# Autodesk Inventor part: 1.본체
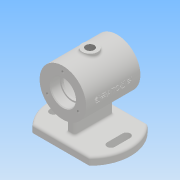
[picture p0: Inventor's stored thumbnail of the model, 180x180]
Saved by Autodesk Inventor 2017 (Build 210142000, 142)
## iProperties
Part Number: 1.본체
Material: 일반
Document SubType Name: Modeling
Designer: user
Density: 1 g/cm^3
Appearance: 기본값
Author: user
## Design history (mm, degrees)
sketch "스케치1"
  geometry: L1 (-37.5, -36.742)-(-37.5, 36.742); L2 (37.5, 36.742)-(37.5, -36.742); L3 (-37.5, -36.742)-(37.5, -36.742); L4 (-37.5, 36.742)-(37.5, 36.742); L5 (37.5, 36.742)-(0, 36.742); L6 (-10, 36.742)-(10, 36.742); L7 (-10, 36.742)-(10, 36.742); L8 (-52.5, 0)-(52.5, 0); L9 (0, 0)-(0, -37); L10 (10, -37)-(-10, -37); L11 (10, -37)-(-10, -37); L12 (10, -32)-(-10, -32); L13 (-10, -42)-(10, -42); L14 (-10, 42)-(10, 42); L15 (10, 32)-(-10, 32); A1 r 52.5 centre (0, 0) between (37.5, 36.742) and (-37.5, 36.742); A2 r 52.5 centre (0, 0) between (37.5, -36.742) and (37.5, 36.742); A3 r 52.5 centre (0, 0) between (-37.5, -36.742) and (37.5, -36.742); A4 r 52.5 centre (0, 0) between (-37.5, 36.742) and (-37.5, -36.742); A5 r 5 centre (10, -37) between (10, -42) and (10, -32); A6 r 5 centre (-10, -37) between (-10, -32) and (-10, -42); A7 r 5 centre (10, 37) between (10, 32) and (10, 42); A8 r 5 centre (-10, 37) between (-10, 42) and (-10, 32); 3 further points
  constraints: 34 end point, 18 point on circle, 8 centre point, 6 symmetric about line, 5 coincident, 5 midpoint, 4 tangent, 3 horizontal, 3 parallel, 1 collinear, 1 vertical, 2 other
  dimensions: "d0" = 105 diameter of A1; "d2" = 73.48469 distance of L2.start L2.end; "d3" = 75 distance between parallel lines of L2 L1; "d13" = 37.5 distance of L2.start L5.end; "d75" = 37 distance of L9.end L9.start; "d76" = 20 distance of L10.start L10.end; "d77" = 20 distance of L6.start L6.end; "d78" = 10 diameter of A6
extrude "돌출1" new body sketch "스케치1" distance "d4" = 10; taper "d5" = 0 deg
sketch "스케치2"
  geometry: L1 (0, 0)-(0, 62); L2 (-25, 0)-(25, 0); L3 (-25, 0)-(-25, 62); L4 (-25, 62)-(25, 62); L5 (25, 62)-(25, 0)
  constraints: 10 end point, 2 midpoint, 2 vertical, 1 horizontal, 1 parallel, 1 perpendicular
  dimensions: "d6" = 62 distance of L1.end L1.start; "d7" = 50 distance of L2.start L2.end
extrude "돌출2" join sketch "스케치2" stored distance "d8" = 10; taper "d9" = 0 deg
sketch "스케치3"
  geometry: L1 (-5, 62)-(5, 62) reference; C1 r 30 at (0, 62); 2 further points
  constraints: 1 centre point, 1 coincident, 1 midpoint
  dimensions: "d10" = 60 diameter of C1
extrude "돌출3" join sketch "스케치3" stored distance "d11" = 70; taper "d12" = 0 deg
sketch "스케치4"
  geometry: L1 (35, 32)-(35, 92) reference; L2 (35, 62)-(-35, 62); L3 (-35, 92)-(-35, 32) reference; L4 (35, 62)-(35, 78); L5 (35, 78)-(23, 78); L6 (23, 78)-(23, 76); L7 (23, 76)-(20, 76); L8 (20, 76)-(20, 87); L9 (20, 87)-(-20, 87); L10 (-20, 87)-(-20, 76); L11 (-20, 76)-(-23, 76); L12 (-23, 76)-(-23, 78); L13 (-23, 78)-(-35, 78); L14 (-35, 78)-(-35, 62); 1 further point
  constraints: 24 end point, 7 perpendicular, 6 point on line, 2 midpoint, 1 collinear, 1 vertical
  dimensions: "d20" = 12 distance of L4.end L5.end; "d21" = 28 diameter of L7 L2; "d22" = 32 diameter of L5 L2; "d23" = 50 diameter of L9 L2; "d24" = 3 distance of L6.end L7.end; "d25" = 40 distance of L8.end L9.end
node "작업 평면1"
sketch "스케치5"
  geometry: C1 r 10 at (0, 0); 1 further point
  constraints: 1 centre point, 1 coincident
  dimensions: "d28" = 20 diameter of C1
extrude "돌출5" join sketch "스케치5" distance "d29" = 20; taper "d30" = 0 deg
revolve "회전2" stored, may be unused: angle "d31" = 90 deg
sketch "스케치6"
  geometry: C1 r 10 at (0, 0) reference; 1 further point
  constraints: 1 coincident
hole "구멍1" sketch "스케치6" at (0, 0) diameter "d32" = 10.917; stored, may be unused: countersink angle "d36" = 90 deg, drill point angle "d38" = 118 deg; dims "d33" = 24, "d34" = 4, "d35" = 2, "d37" = 29.1
sketch "스케치7" dims "d48" = 46
  geometry: L1 (-23, 0)-(0, 0); L2 (11.5, -19.919)-(0, 0); L3 (11.5, 19.919)-(0, 0); L4 (0, 0)-(62, 0); C1 r 16 at (0, 0) reference; C2 r 30 at (0, 0) reference; 6 further points
  constraints: 8 end point, 6 coincident, 2 horizontal, 1 horizontal alignment, 1 point on line, 22 other
  dimensions: "d46" = 360 deg dimension on point (0, 0) L1.start (derived); "d74" = 23 distance of L3.start L3.end
hole "구멍2" sketch "스케치7" at (-23, 0), (11.5, -19.919), (11.5, 19.919) diameter "d49" = 3.242; stored, may be unused: countersink angle "d53" = 90 deg, drill point angle "d55" = 118 deg; dims "d50" = 8, "d51" = 4, "d52" = 2, "d54" = 10
fillet "모깎기1" dims "d56" = 3
fillet "모깎기2" dims "d57" = 3
chamfer "모따기1" distance "d58" = 1; stored, may be unused: second distance "d59" = 2, angle "d60" = 45 deg
chamfer "모따기2" distance "d61" = 1; stored, may be unused: second distance "d62" = 2, angle "d63" = 45 deg
fillet "모깎기3" dims "d64" = 3
fillet "모깎기4" dims "d65" = 3
fillet "모깎기5" dims "d66" = 3
fillet "모깎기6" dims "d67" = 3
fillet "모깎기7" dims "d68" = 0.3
node "작업 평면2"
sketch "스케치8"
  geometry: L1 (0, 0)-(0, 95); L2 (-10, 95)-(10, 95) reference; L3 (35, 32)-(35, 92) reference; L4 (-35, 92)-(-35, 32) reference; L5 (-35, 62)-(35, 62); 2 further points
  constraints: 4 end point, 4 midpoint, 1 coincident, 1 other
  dimensions: "d85" = 35 distance between parallel lines of L4 L1 (derived); "d86" = 30 distance from line of L4.start L5 (derived)
feature "엠보싱1" sketch "스케치8" dims "d0" = 105, "d2" = 73.48469, "d3" = 75, "d13" = 37.5, "d72" = 0.5, "d73" = 0, "d75" = 37, "d76" = 20, "d77" = 20, "d78" = 10
sketch "스케치9"
  geometry: L1 (37.5, -35.496)-(37.5, 35.496) reference; L2 (-37.5, -35.496)-(-37.5, 35.496) reference; L3 (-37.5, 0)-(37.5, 0); L4 (0, 0)-(0, 37); L5 (-10, 37)-(10, 37); L6 (-10, 37)-(10, 37); L7 (-10, 32)-(10, 32); L8 (10, 42)-(-10, 42); L9 (-10, -32)-(10, -32); L10 (10, -42)-(-10, -42); A1 r 52.5 centre (0, 0) between (36.591, 37.648) and (-36.591, 37.648) reference; A2 r 5 centre (-10, 37) between (-10, 42) and (-10, 32); A3 r 5 centre (10, 37) between (10, 32) and (10, 42); A4 r 5 centre (10, -37) between (10, -42) and (10, -32); A5 r 5 centre (-10, -37) between (-10, -32) and (-10, -42); 1 further point
  constraints: 18 end point, 8 point on circle, 6 symmetric about line, 4 centre point, 4 midpoint, 4 tangent, 2 coincident, 2 horizontal, 1 parallel, 1 vertical, 2 other
  dimensions: "d79" = 37 distance of L4.end L4.start; "d80" = 20 distance of L5.start L5.end; "d81" = 10 diameter of A3
extrude "돌출6" cut sketch "스케치9" distance "d82" = 20; taper "d83" = 0 deg
node "솔리드1"
mirror "미러1"
other parameters: "d27" = 95, "d69" = 41
